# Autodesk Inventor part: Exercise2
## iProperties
Shininess: 64.0
Length Units: 11269
Angle Units: 11279
Time Units: 11290
Mass Units: 11283
Length Display Precision: 3
Angle Display Precision: 2
Compacted: True
Created: 2002-02
Part Number: Exercise2
Document SubType Name: Modeling
Density: 0.0
Volumn: 0.0
Area: 0.0
PropertySet Name: Model Information
Control State: 0
Master: False
Checked Out: False
